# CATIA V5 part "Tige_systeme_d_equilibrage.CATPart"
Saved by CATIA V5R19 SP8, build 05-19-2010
Part number: Tige_systeme_d_equilibrage
Bounding box of the stored display mesh (mm): x -142 to -79.944, y -547.188 to 42.638, z 1182.598 to 1300.066
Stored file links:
  G:\EU_thinkMotion\CFAO_2010\MMS_groupe2\MMS_groupe2\OK\nrosalie\nrosalie_cfao_support_d_arme_legere_final\Tige_systeme_d_equilibrage.CATPart
  G:\EU_thinkMotion\CFAO_2010\MMS_groupe2\MMS_groupe2\OK\nrosalie\nrosalie_cfao_support_d_arme_legere_final\nrosalie_Support_d_arme_legere.CATProduct
  G:\EU_thinkMotion\CFAO_2010\MMS_groupe2\MMS_groupe2\OK\nrosalie\nrosalie_cfao_support_d_arme_legere_final\Squelette_systeme_d_equilibrage.CATPart
  G:\EU_thinkMotion\CFAO_2010\MMS_groupe2\MMS_groupe2\OK\nrosalie\nrosalie_cfao_support_d_arme_legere_final\Squelette_piece_support.CATPart
  G:\EU_thinkMotion\CFAO_2010\MMS_groupe2\MMS_groupe2\OK\nrosalie\nrosalie_cfao_support_d_arme_legere_final\Piece_de_support.CATPart
  G:\EU_thinkMotion\CFAO_2010\MMS_groupe2\MMS_groupe2\OK\nrosalie\nrosalie_cfao_support_d_arme_legere_final\Chambre_systeme_equilibrage.CATPart
  C:\Espace travail\Cours 2A MMS\CFAO\Projet CFAO\Modele CAO\8-01-2010\Symmetry of Piece_de_support.CATPart
  G:\EU_thinkMotion\CFAO_2010\MMS_groupe2\MMS_groupe2\OK\nrosalie\nrosalie_cfao_support_d_arme_legere_final\Squelette_bras.CATPart
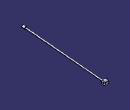
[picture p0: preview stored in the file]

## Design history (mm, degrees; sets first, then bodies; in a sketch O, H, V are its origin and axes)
Set1
  Plane1: linked copy from another document
  Point1: linked copy from another document
  Line1: linked copy from another document
  Plane2: linked copy from another document
  DatumCurve1 to DatumCurve3: linked copy from another document
  DatumPoint1 to DatumPoint3: linked copy from another document
  DatumSurface1: linked copy from another document
  DatumCurve4: linked copy from another document
  DatumPoint4: linked copy from another document
Body1 (main body)
  Plane3: type OffsetPt, RefPlane Plane2, RefPoint Point1
  Sketch1 on Plane3, origin (0, 0, 1197.4749), H (1, 0, 0), V (0, 1, 0)
    line L1 (-142, 42.7611) -> (-117, 42.7611)
    line L2 (-117, 42.7611) -> (-117, 32.7611)
    line L3 (-117, 32.7611) -> (-142, 32.7611)
    line L4 (-142, 32.7611) -> (-142, 42.7611)
    reference projected point E1 (-127, 27.7611) from Point1
    reference projected point E2 (-127, 27.7611) from Point1
    length L3 = 25
    distance E1 L3 = 5
    distance L1 L3 = 10
    distance L2 E2 = 10
    horizontal: L1 H, L3 H
    vertical: L2 V, L4 V
  Shaft1: profile Sketch1, axis edge of DatumCurve3, angle 360
  Sketch2 on Plane1, origin (11.6693, -155.2391, 21.3889), H (0.9978, 0.0666, 0.0021), V (-0.0128, 0.1605, 0.987)
    circle A1 centre (-123.7158, 1191.8855) radius 5
    reference projected point E1 (-123.7158, 1191.8855) from Point1
    radius A1 = 5
    concentricity: A1 E1
  Pad1: profile Sketch2, direction (0.0654, -0.9848, 0.1609), up to face of DatumSurface1, offset -30, opposite side up to face of Shaft1 from Sketch1.L1
  Sketch3 on end face of Pad1, origin (58.9857, -733.7265, 80.1228), H (0.9978, 0.0666, 0.0021), V (-0.0128, 0.1605, 0.987)
    circle A1 centre (-132.5226, 1227.3411) radius 9
    reference projected circle E1 centre (-132.5226, 1227.3411) radius 5 from edge [end face of Pad1 | face of Pad1 from Sketch2.A1]
    radius A1 = 9
    concentricity: A1 E1
  Pad2: profile Sketch3, direction (-0.0654, 0.9848, -0.1609), length 20
  Plane4: type 3Points, Element1 DatumPoint1, Element2 DatumPoint2, Element3 DatumPoint3
  Line2: type PtPt, FirstPoint DatumPoint4, SecondPoint Point1, Start 500, End 500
